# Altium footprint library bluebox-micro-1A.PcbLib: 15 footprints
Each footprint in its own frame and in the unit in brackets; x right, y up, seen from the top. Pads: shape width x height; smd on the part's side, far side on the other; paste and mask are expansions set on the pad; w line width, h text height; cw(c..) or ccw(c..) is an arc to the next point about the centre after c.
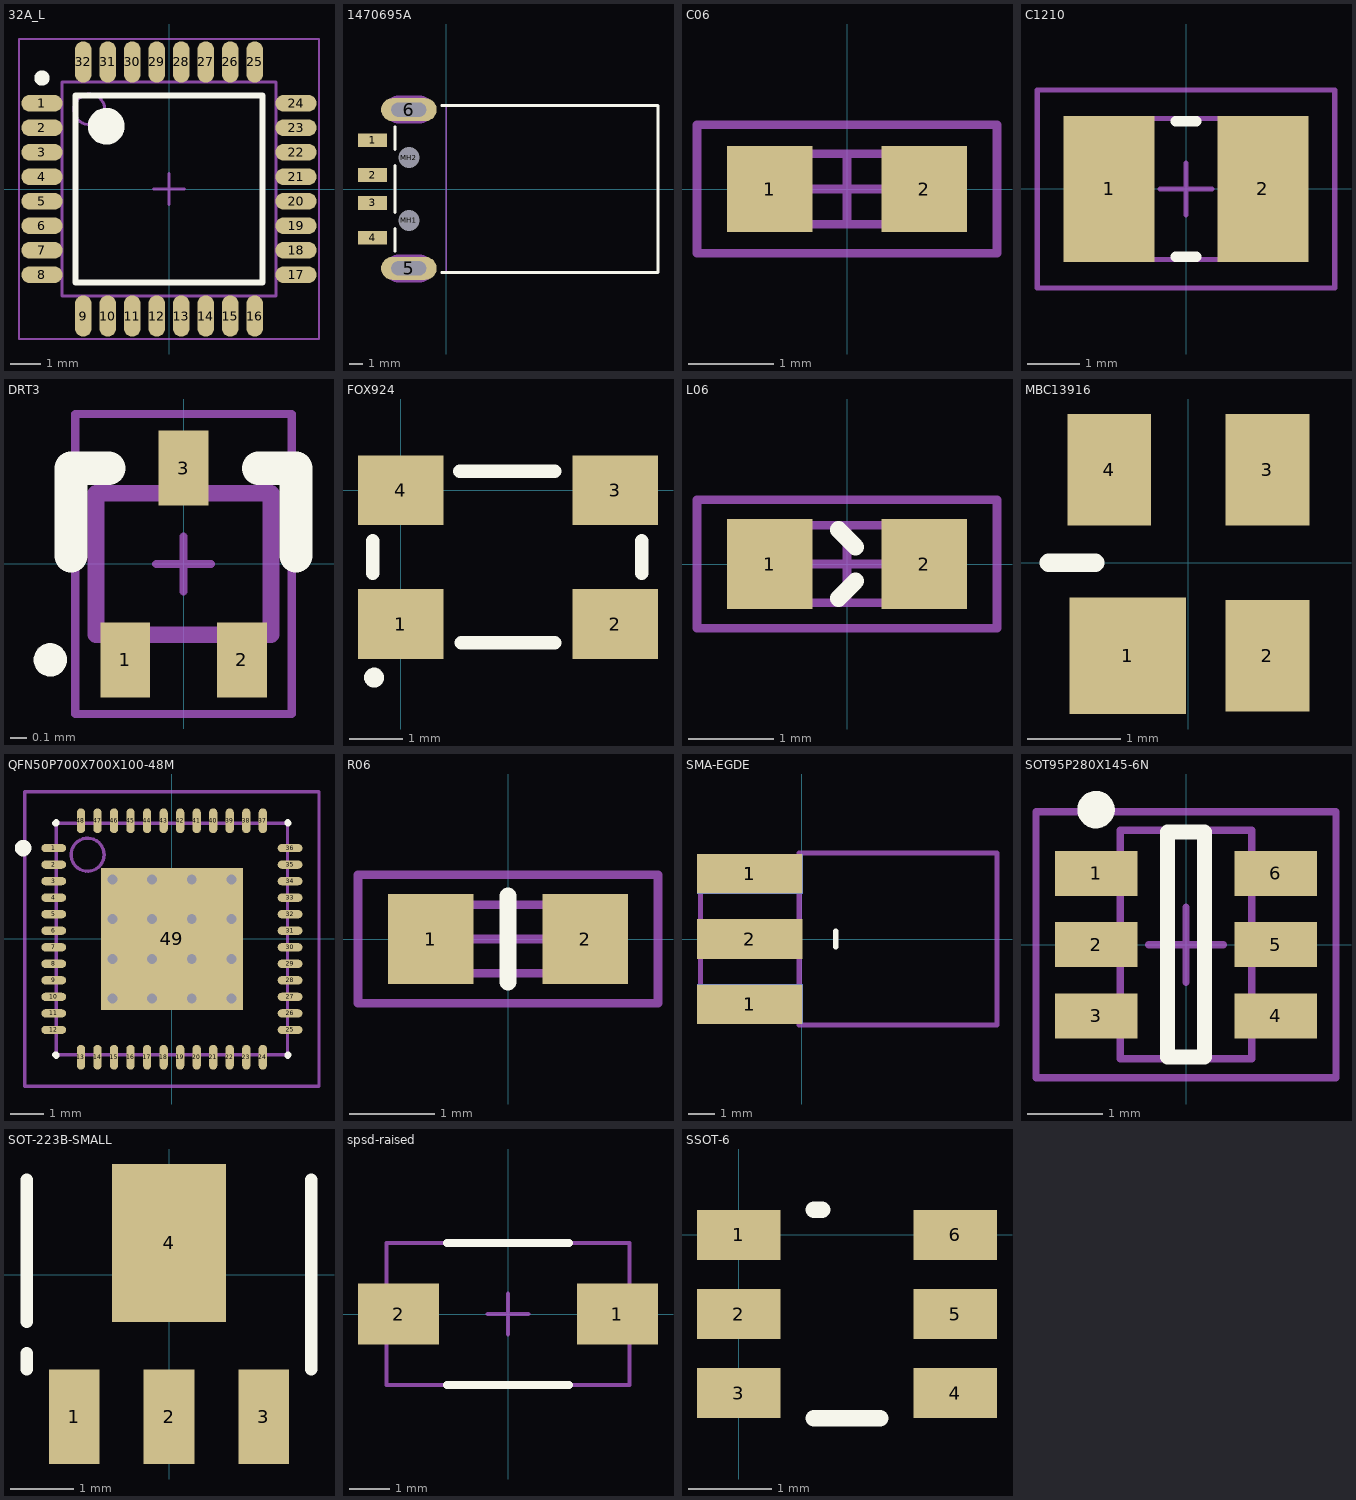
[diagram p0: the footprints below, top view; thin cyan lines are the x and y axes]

## 32A_L [mm]
pads (32):
  oval 1.35x0.55 smd: 1(-4.15,2.8) 2(-4.15,2) 3(-4.15,1.2) 4(-4.15,0.4) 5(-4.15,-0.4) 6(-4.15,-1.2) 7(-4.15,-2) 8(-4.15,-2.8) 17(4.15,-2.8) 18(4.15,-2) 19(4.15,-1.2) 20(4.15,-0.4) 21(4.15,0.4) 22(4.15,1.2) 23(4.15,2) 24(4.15,2.8)
  oval 0.55x1.35 smd: 9(-2.8,-4.15) 10(-2,-4.15) 11(-1.2,-4.15) 12(-0.4,-4.15) 13(0.4,-4.15) 14(1.2,-4.15) 15(2,-4.15) 16(2.8,-4.15) 25(2.8,4.15) 26(2,4.15) 27(1.2,4.15) 28(0.4,4.15) 29(-0.4,4.15) 30(-1.2,4.15) 31(-2,4.15) 32(-2.8,4.15)
Top Overlay:
  circle w0.25: c-4.15,3.625 r0.125
  circle w0.6: c-2.05,2.05 r0.3
  lines w0.2: -3.05,-3.05 -3.05,3.05 3.05,3.05 3.05,-3.05 -3.05,-3.05
Mechanical 13:
  circle w0.1: c-2.6,2.6 r0.5
  lines w0.1: -3.5,-3.5 -3.5,3.5 3.5,3.5 3.5,-3.5 -3.5,-3.5
Mechanical 15:
  lines w0.05: -4.9,-4.9 -4.9,4.9 4.9,4.9 4.9,-4.9 -4.9,-4.9
  lines w0.1: -0.5,0 0.5,0 ; 0,-0.5 0,0.5
3D body: height 1.2, standoff 0, extent -3.5,-3.5 3.5,3.5

## 1470695A [mm]
pads (8):
  rect 2.1x1 smd: 1(-5.3,3.5) 2(-5.3,1) 3(-5.3,-1) 4(-5.3,-3.5)
  oval 4x1.65 hole 1 slot 2.5 at 0 deg: 5(-2.7,-5.7) 6(-2.7,5.7)
  round 1.2 hole 1.5 unplated: MH1(-2.7,-2.25) MH2(-2.7,2.25)
Top Overlay:
  lines w0.2: -3.7,-4.475 -3.7,-2.83 ; -3.7,-1.68 -3.7,1.68 ; -3.7,2.83 -3.7,4.475 ; -0.33,-6 15.2,-6 15.2,6 -0.33,6
Mechanical 1:
  lines w0.1: 0,-6 0,6
  lines w1: -3.45,-5.7 -1.95,-5.7 ; -3.45,5.7 -1.95,5.7
  text "PCB Edge" at 0.473,-5.173 h0.25
Mechanical 2:
  lines w2.016: -3.45,-5.7 -1.95,-5.7 ; -3.45,5.7 -1.95,5.7

## C06 [mm]
pads (2):
  rect 1x1 smd: 1(-0.9,0) 2(0.9,0)
Mechanical 13:
  lines w0.1: -0.8,-0.41 -0.8,0.41 0.8,0.41 0.8,-0.41 -0.8,-0.41
Mechanical 15:
  lines w0.1: -0.41,0 0.41,0 ; 0,-0.41 0,0.41 ; -1.75,-0.75 -1.75,0.75 1.75,0.75 1.75,-0.75 -1.75,-0.75
3D body: height 0.82, standoff 0, extent -0.8,-0.41 0.8,0.41

## C1210 [mm]
pads (2):
  rect 1.75x2.8 smd: 1(-1.475,0) 2(1.475,0)
Top Overlay:
  lines w0.2: -0.2,-1.3 0.2,-1.3 ; -0.2,1.3 0.2,1.3
Mechanical 13:
  lines w0.1: -1.75,-1.35 -1.75,1.35 1.75,1.35 1.75,-1.35 -1.75,-1.35
Mechanical 15:
  lines w0.1: -0.5,0 0.5,0 ; 0,-0.5 0,0.5 ; -2.85,-1.9 -2.85,1.9 2.85,1.9 2.85,-1.9 -2.85,-1.9
3D body: height 2.7, standoff 0, extent -1.75,-1.35 1.75,1.35

## DRT3 [mm]
pads (3):
  rect 0.3x0.45 smd: 1(-0.35,-0.575) 2(0.35,-0.575) 3(0,0.575)
Top Overlay:
  circle w0.1: c-0.8,-0.575 r0.05
  lines w0.2: -0.675,0.05 -0.675,0.575 -0.45,0.575 ; 0.45,0.575 0.675,0.575 0.675,0.05
Mechanical 13:
  lines w0.1: -0.525,-0.425 0.525,-0.425 0.525,0.425 -0.525,0.425 -0.525,-0.425
Mechanical 15:
  lines w0.05: -0.165,0 0.165,0 ; 0,-0.165 0,0.165 ; -0.65,-0.9 -0.65,0.9 0.65,0.9 0.65,-0.9 -0.65,-0.9
3D body: height 0.5, standoff 0, extent -0.524,-0.424 0.524,0.424

## FOX924 [mm]
pads (4):
  rect 1.6x1.3 smd: 1(0,-2.5) 2(4,-2.5) 3(4,0) 4(0,0)
Top Overlay:
  circle w0.254: c-0.5,-3.5 r0.059
  lines w0.254: -0.525,-1.55 -0.525,-0.95 ; 1.1,0.35 2.875,0.35 ; 1.125,-2.85 2.875,-2.85 ; 4.5,-1.55 4.5,-0.95
3D body: height 1.5, standoff 0, extent -0.525,-2.825 4.5,0.35

## L06 [mm]
pads (2):
  rect 1x1.05 smd: 1(-0.9,0) 2(0.9,0)
Top Overlay:
  lines w0.2: -0.1,-0.4 0.1,-0.2 ; -0.1,0.4 0.1,0.2
Mechanical 13:
  lines w0.1: -0.85,-0.45 0.85,-0.45 0.85,0.45 -0.85,0.45 -0.85,-0.45
Mechanical 15:
  lines w0.1: -0.45,0 0.45,0 ; 0,-0.45 0,0.45 ; -1.75,-0.75 1.75,-0.75 1.75,0.75 -1.75,0.75 -1.75,-0.75
3D body: height 0.9, standoff 0, extent -0.85,-0.45 0.85,0.45

## MBC13916 [mm]
pads (4):
  rect 1.25x1.25 smd: 1(-0.65,-1)
  rect 0.9x1.2 smd: 2(0.85,-1) 3(0.85,1) 4(-0.85,1)
Top Overlay:
  lines w0.2: -1.5,0 -1,0

## QFN50P700X700X100-48M [mm]
pads (49):
  oval 0.75x0.25 smd mask+0.154: 1(-3.575,2.75) 2(-3.575,2.25) 3(-3.575,1.75) 4(-3.575,1.25) 5(-3.575,0.75) 6(-3.575,0.25) 7(-3.575,-0.25) 8(-3.575,-0.75) 9(-3.575,-1.25) 10(-3.575,-1.75) 11(-3.575,-2.25) 12(-3.575,-2.75) 25(3.575,-2.75) 26(3.575,-2.25) 27(3.575,-1.75) 28(3.575,-1.25) 29(3.575,-0.75) 30(3.575,-0.25) 31(3.575,0.25) 32(3.575,0.75) 33(3.575,1.25) 34(3.575,1.75) 35(3.575,2.25) 36(3.575,2.75)
  oval 0.25x0.75 smd mask+0.154: 13(-2.75,-3.575) 14(-2.25,-3.575) 15(-1.75,-3.575) 16(-1.25,-3.575) 17(-0.75,-3.575) 18(-0.25,-3.575) 19(0.25,-3.575) 20(0.75,-3.575) 21(1.25,-3.575) 22(1.75,-3.575) 23(2.25,-3.575) 24(2.75,-3.575) 37(2.75,3.575) 38(2.25,3.575) 39(1.75,3.575) 40(1.25,3.575) 41(0.75,3.575) 42(0.25,3.575) 43(-0.25,3.575) 44(-0.75,3.575) 45(-1.25,3.575) 46(-1.75,3.575) 47(-2.25,3.575) 48(-2.75,3.575)
  rect 4.3x4.3 smd mask+0.154: 49(0,0)
via 1.8,-1.8 diameter 0.5 hole 0.3
via 0.6,-1.8 diameter 0.5 hole 0.3
via -0.6,-1.8 diameter 0.5 hole 0.3
via -1.8,-1.8 diameter 0.5 hole 0.3
via 1.8,-0.6 diameter 0.5 hole 0.3
via 0.6,-0.6 diameter 0.5 hole 0.3
via -0.6,-0.6 diameter 0.5 hole 0.3
via -1.8,-0.6 diameter 0.5 hole 0.3
via 1.8,0.6 diameter 0.5 hole 0.3
via 0.6,0.6 diameter 0.5 hole 0.3
via -0.6,0.6 diameter 0.5 hole 0.3
via -1.8,0.6 diameter 0.5 hole 0.3
via 1.8,1.8 diameter 0.5 hole 0.3
via 0.6,1.8 diameter 0.5 hole 0.3
via -0.6,1.8 diameter 0.5 hole 0.3
via -1.8,1.8 diameter 0.5 hole 0.3
Top Overlay:
  circle w0.25: c-4.5,2.75 r0.125
  lines w0.2: -3.525,-3.5 -3.5,-3.5 -3.5,-3.525 ; -3.525,3.5 -3.5,3.5 -3.5,3.525 ; 3.5,-3.525 3.5,-3.5 3.525,-3.5 ; 3.5,3.525 3.5,3.5 3.525,3.5
Mechanical 13:
  circle w0.1: c-2.55,2.55 r0.5
  lines w0.1: -3.5,-3.5 -3.5,3.5 3.5,3.5 3.5,-3.5 -3.5,-3.5
Mechanical 15:
  lines w0.1: -0.5,0 0.5,0 ; 0,-0.5 0,0.5 ; -4.45,-4.45 -4.45,4.45 4.45,4.45 4.45,-4.45 -4.45,-4.45
3D body: height 1, standoff 0.01, extent -3.5,-3.5 3.5,3.5

## R06 [mm]
pads (2):
  rect 1x1.05 smd: 1(-0.9,0) 2(0.9,0)
Top Overlay:
  lines w0.2: 0,-0.5 0,0.5
Mechanical 13:
  lines w0.1: -0.8,-0.4 0.8,-0.4 0.8,0.4 -0.8,0.4 -0.8,-0.4
Mechanical 15:
  lines w0.1: -0.4,0 0.4,0 ; 0,-0.4 0,0.4 ; -1.75,-0.75 1.75,-0.75 1.75,0.75 -1.75,0.75 -1.75,-0.75
3D body: height 0.55, standoff 0, extent -0.8,-0.4 0.8,0.4

## SMA-EGDE [mm]
pads (5):
  rect 4.06x1.52 smd: 1(-2,-2.5) 1(-2,2.5) 2(-2,0)
  rect 4.06x1.52 smd far side: 1(-2,-2.5) 1(-2,2.5)
Top Overlay:
  lines w0.2: 1.3,-0.3 1.3,0.3
Mechanical 15:
  lines w0.2: -0.1,-3.1 -0.1,3.1 ; -0.1,-3.1 -0.1,-3.3 7.5,-3.3 7.5,3.3 -0.1,3.3 -0.1,3.1 ; -0.1,-3.1 -3.9,-3.1 -3.9,3.1 -0.1,3.1

## SOT95P280X145-6N [mm]
pads (6):
  rect 1.1x0.6 smd: 1(-1.2,0.95) 2(-1.2,0) 3(-1.2,-0.95) 4(1.2,-0.95) 5(1.2,0) 6(1.2,0.95)
Top Overlay:
  circle w0.25: c-1.2,1.8 r0.125
  lines w0.2: -0.25,-1.5 0.25,-1.5 0.25,1.5 -0.25,1.5 -0.25,-1.5
Mechanical 13:
  lines w0.1: -0.875,-1.525 -0.875,1.525 0.875,1.525 0.875,-1.525 -0.875,-1.525
Mechanical 15:
  lines w0.1: -0.5,0 0.5,0 ; 0,-0.5 0,0.5 ; -2,-1.775 -2,1.775 2,1.775 2,-1.775 -2,-1.775
3D body: height 1.45, standoff 0, extent -0.875,-1.525 0.875,1.525

## SOT-223B-SMALL [mm]
pads (4):
  rect 0.8x1.5 smd: 1(-1.5,-2.25) 2(0,-2.25) 3(1.5,-2.25)
  rect 1.8x2.5 smd: 4(0,0.5)
Top Overlay:
  lines w0.2: -2.25,-1.5 -2.25,-1.25 ; -2.25,-0.75 -2.25,1.5 ; 2.25,-1.5 2.25,1.5

## spsd-raised [mm]
pads (2):
  rect 2x1.5 smd: 1(2.7,0) 2(-2.7,0)
Top Overlay:
  lines w0.2: -1.5,-1.75 1.5,-1.75 ; -1.5,1.75 1.5,1.75
Mechanical 13:
  lines w0.1: -3,-1.75 3,-1.75 3,1.75 -3,1.75 -3,-1.75
Mechanical 15:
  lines w0.1: -0.5,0 0.5,0 ; 0,-0.5 0,0.5

## SSOT-6 [mm]
pads (6):
  rect 1x0.6 smd: 1(0,0) 2(0,-0.95) 3(0,-1.9) 4(2.6,-1.9) 5(2.6,-0.95) 6(2.6,0)
Top Overlay:
  lines w0.2: 0.9,-2.2 1.7,-2.2 ; 0.9,0.3 1,0.3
